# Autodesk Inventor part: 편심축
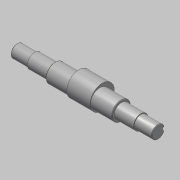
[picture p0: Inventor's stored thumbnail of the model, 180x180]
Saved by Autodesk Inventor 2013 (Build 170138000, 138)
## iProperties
Created: 2015-10
Part Number: 편심축
Document SubType Name: Modeling
Designer: mdu
Density: 7.86 g/cm^3
Material: 강철, 연강
Mass: 1327.93 g
Surface Area: 248.524 cm^2
Volume: 168.947 cm^3
Author: mdu
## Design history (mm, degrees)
sketch "스케치1"
  geometry: L1 (-20.5, -41.331)-(-20.5, 32.669) reference; L2 (7.5, -30.031)-(7.5, 21.369) reference; L3 (135.5, -30.331)-(135.5, 21.669) reference; L4 (121.5, 21.369)-(121.5, -30.031) reference; L5 (184.5, -4.331)-(-57.5, -4.331); L6 (184.5, -4.331)-(184.5, 6.669); L7 (154.5, 8.169)-(121.5, 8.169); L8 (121.5, 8.169)-(121.5, 11.669); L9 (121.5, 11.669)-(7.5, 11.669); L10 (7.5, 11.669)-(7.5, 8.169); L11 (7.5, 8.169)-(-27.5, 8.169); L12 (-27.5, 8.169)-(-27.5, 6.669); L13 (-27.5, 6.669)-(-57.5, 6.669); L14 (-57.5, 6.669)-(-57.5, -4.331); L15 (154.5, 8.169)-(154.5, 6.669); L16 (154.5, 6.669)-(184.5, 6.669); C1 r 32.5 at (64.5, -4.331) reference; 1 further point
  constraints: 24 end point, 8 perpendicular, 5 point on line, 3 parallel, 2 collinear
  dimensions: "d1" = 25 diameter of L11 L5; "d2" = 32 diameter of L9 L5; "d3" = 22 diameter of L13 L5; "d4" = 35 distance of L10.end L11.end; "d5" = 30 distance of L12.end L13.end; "d15" = 33 distance of L7.start L7.end; "d26" = 30 distance of L15.end L6.end
revolve "회전1" sketch "스케치1" stored, may be unused: angle "d6" = 90 deg
node "작업 평면1"
sketch "스케치2"
  geometry: C1 r 16 at (0, 0) reference; C2 r 20.75 at (0, 4)
  constraints: 1 centre point, 1 vertical alignment
  dimensions: "d34" = 4 distance of C2.centre C1.centre; "d35" = 41.5 diameter of C2
extrude "돌출1" join sketch "스케치2" stored distance "d9" = 40; taper "d10" = 0 deg
chamfer "모따기1" distance "d11" = 1; stored, may be unused: second distance "d12" = 2, angle "d13" = 45 deg
node "작업 평면2"
sketch "스케치3"
  geometry: L1 (-15, -10)-(-15, 10) reference; L2 (-15, 3)-(0, 3); L3 (0, -3)-(-15, -3); A1 r 3 centre (0, 0) between (0, -3) and (0, 3); 2 further points
  constraints: 4 end point, 2 perpendicular, 2 point on circle, 2 point on line, 2 tangent, 1 centre point, 1 horizontal alignment, 1 midpoint
  dimensions: "d16" = 18 dimension on A1 L1; "d17" = 6 distance between parallel lines of L3 L2
extrude "돌출2" cut sketch "스케치3" distance "d18" = 3.5; taper "d19" = 0 deg
node "작업 평면3"
node "솔리드1"
mirror "대칭1"
node "참조1"
node "참조2"
node "참조3"
node "참조4"
node "참조5"
other parameters: "d30" = 35
